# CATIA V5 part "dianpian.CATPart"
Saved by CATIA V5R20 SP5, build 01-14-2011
Part number: 垫片
Bounding box of the stored display mesh (mm): x -35 to 35, y -25 to 25, z 0 to 20
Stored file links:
  E:\180522132\3.8垫片\dianpian.CATPart
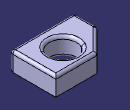
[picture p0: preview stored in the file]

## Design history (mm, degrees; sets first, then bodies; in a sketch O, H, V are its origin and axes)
Body1 (main body)
  Sketch1 on xy-plane, origin (0, 0, 0), H (1, 0, 0), V (0, 1, 0)
    line L1 (35, 25) -> (35, -25)
    line L2 (35, -25) -> (-35, -25)
    line L3 (-35, -25) -> (-35, 0)
    line L4 (-10, 25) -> (35, 25)
    line L5 (-10, 25) -> (-35, 0)
    point P6 (-10.3551, 25.4173)
    length L1 = 50
    length L4 = 45
    length L3 = 25
    vertical: L1 V, L3 V
    horizontal: L2 H, L4 H
    equidistance: L1 L3 O, L2 L4 O
  Pad1: profile Sketch1, direction (0, 0, 1), length 20
  Sketch2 on xy-plane, origin (0, 0, 0), H (1, 0, 0), V (0, 1, 0)
    point P1 (0, 0)
  Hole1: placed by Sketch2, at (0, 0, 0) direction (0, 0, -1), diameter 10, through (limit type 3)
  Sketch3 on end face of Pad1, origin (3.9223, 1.6521, 20), H (1, 0, 0), V (0, 1, 0)
    point P1 (0, 0)
  Hole2: placed by Sketch3, at (3.9223, 1.6521, 20) direction (0, 0, -1), diameter 30, through (limit type 3)
  Fillet1: radius 3, on end face of Pad1; face of Hole2; face of Pad1 from Sketch1.L2; face of Pad1 from Sketch1.L3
